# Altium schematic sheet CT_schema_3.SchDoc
size 298 x 247 mm
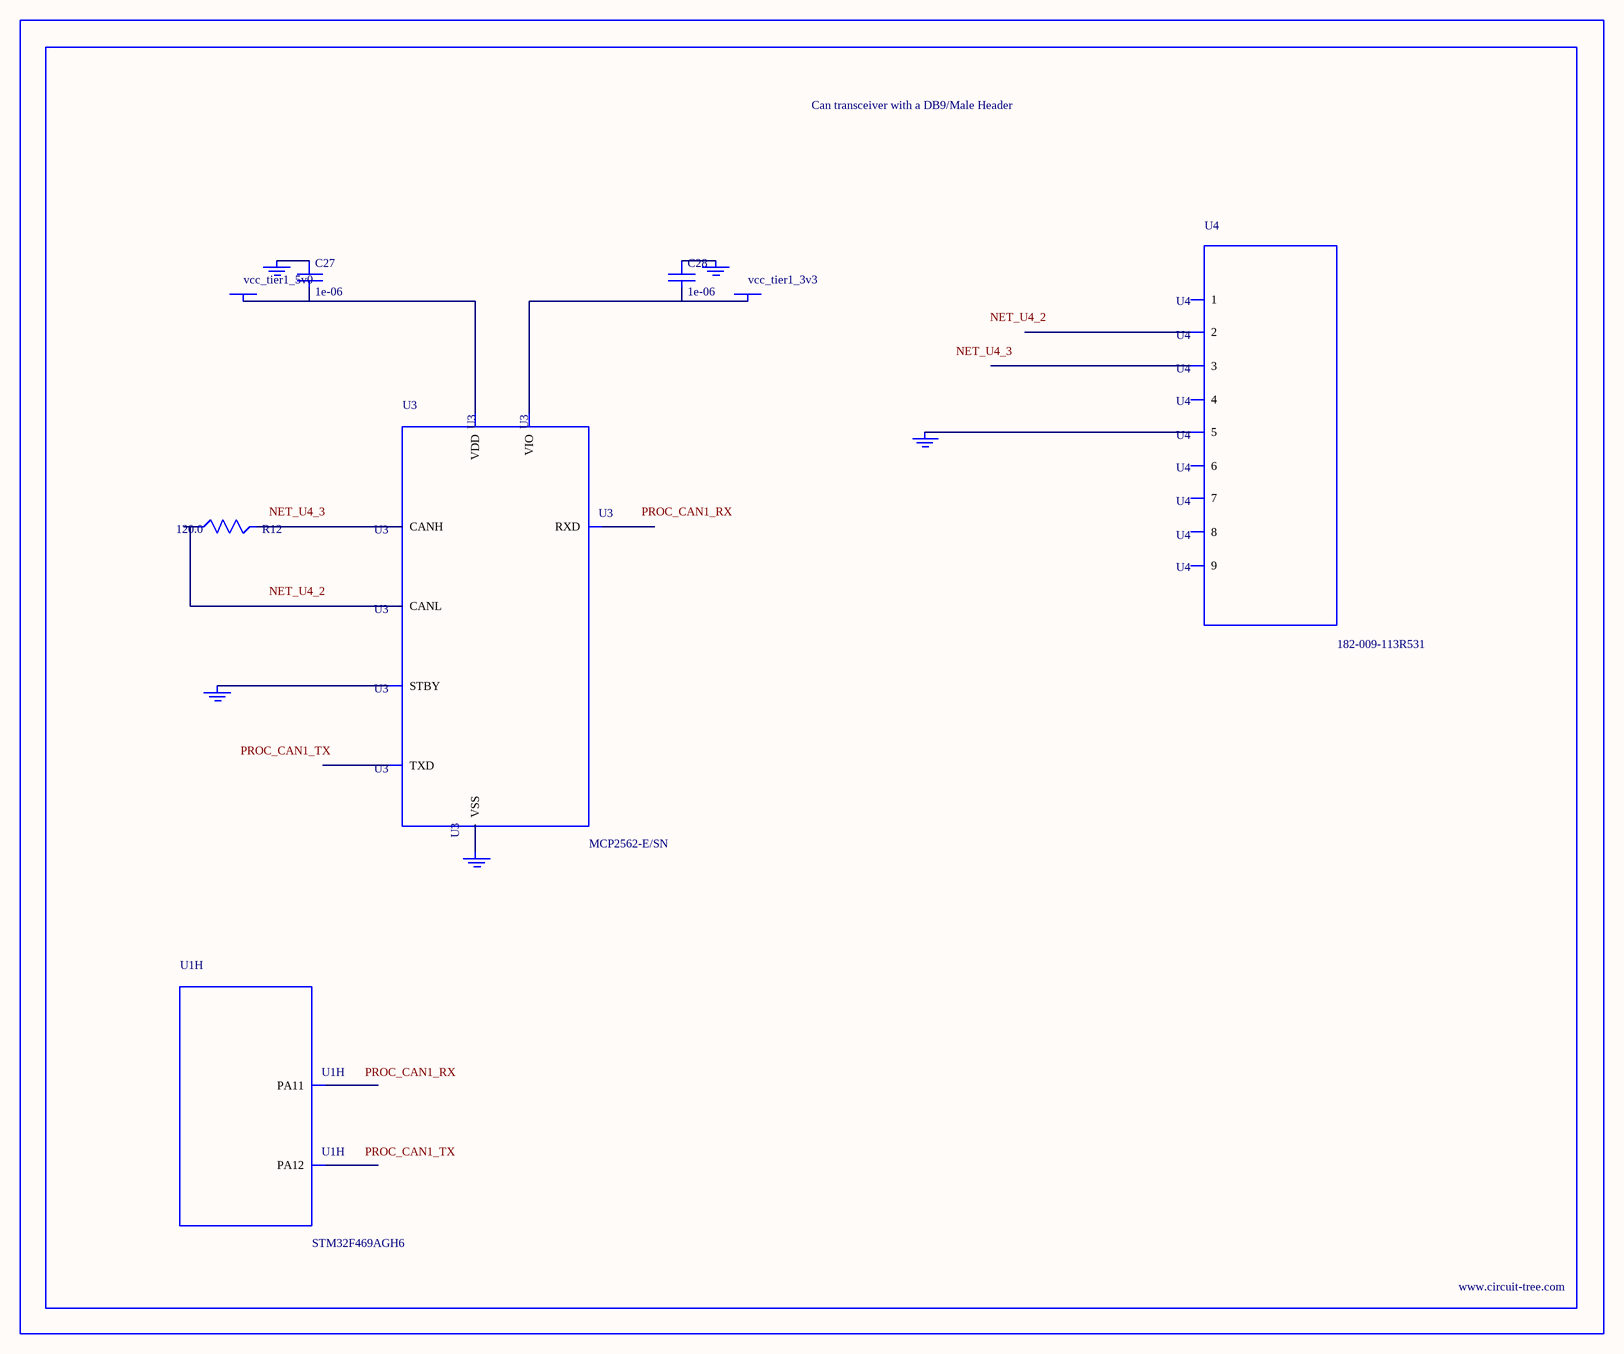
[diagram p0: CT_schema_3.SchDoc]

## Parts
BORDER2  (no value)
C27  1e-06  [C0603]
C28  1e-06  [C0603]
GND_INSTANCE_2_0  (no value)
GND_INSTANCE_2_1  (no value)
GND_INSTANCE_2_2  (no value)
GND_INSTANCE_2_3  (no value)
GND_INSTANCE_2_4  (no value)
POWER_INSTANCE_2_0  vcc_tier1_5v0
POWER_INSTANCE_2_1  vcc_tier1_3v3
R12  120.0  [R0603]
U1  STM32F469AGH6  [UFBGA169]  (part H of 14)
U3  MCP2562-E/SN  [SOIC-8]
U4  182-009-113R531  [182-009-MALE]

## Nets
NetC27_1: C27.1 GND_INSTANCE_2_0.0(GND)
NetC27_2: C27.2 POWER_INSTANCE_2_0.0(PWR) U3.3(VDD)
NetC28_1: C28.1 GND_INSTANCE_2_1.0(GND)
NetC28_2: C28.2 POWER_INSTANCE_2_1.0(PWR) U3.5(VIO)
NetGND_INSTANCE_2_2_0: GND_INSTANCE_2_2.0(GND) U3.8(STBY)
NetGND_INSTANCE_2_3_0: GND_INSTANCE_2_3.0(GND) U3.2(VSS)
NetGND_INSTANCE_2_4_0: GND_INSTANCE_2_4.0(GND) U4.5
NetR12_1: R12.1 U3.6(CANL)
NetR12_2: R12.2 U3.7(CANH)

Not connected (* = marked no-connect by the designer): U1 A12(PA12) A13(PA11); U3 1(TXD) 4(RXD); U4 1 2 3 4 6 7 8 9

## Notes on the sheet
- Labels drawn without touching a wire or pin: NET_U4_2, NET_U4_3, PROC_CAN1_RX, PROC_CAN1_TX

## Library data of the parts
BORDER2 = BORDER_PAGE2
C27 C28 = C0603C105K3RACTU
GND_INSTANCE_2_0-GND_INSTANCE_2_4 = GND
POWER_INSTANCE_2_0 POWER_INSTANCE_2_1 = PWR
R12 = RC0603JR-07120RL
